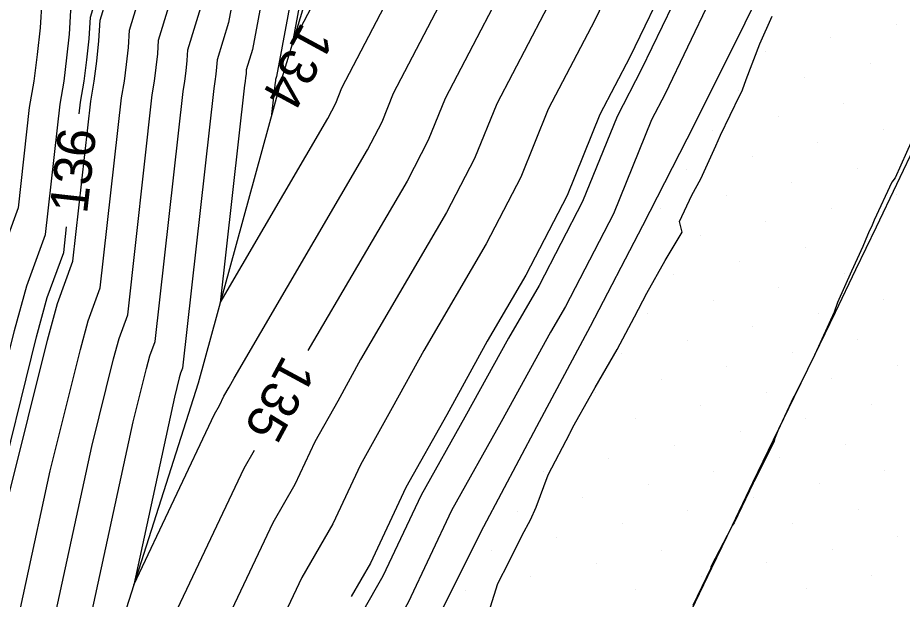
# Model space of a CAD drawing. Extents: x 2354170 to 2357230, y 866100 to 868290.
# Drawn here: x 2355357.59 to 2355404.32, y 866619.62 to 866650.36 of the extents above; entities that cross this region are included whole.
import ezdxf

# ---------------------------------------------------------------- set-up
doc = ezdxf.new("R2010")
doc.units = 0
for name, color, linetype in [('Default', 7, 'Continuous'), ('DTM Contours Major', 7, 'Continuous'), ('DTM Contours Major Text', 7, 'Continuous'), ('DTM Contours Minor', 7, 'Continuous'), ('DTM Contours Minor Text', 7, 'Continuous'), ('Exist DTM Breakline', 7, 'Continuous'), ('Exist DTM Scan Elevation Point', 7, 'Continuous'), ('Exist Roads EOP', 7, 'Continuous'), ('PH Exist DTM Breakline', 7, 'Continuous')]:
    doc.layers.add(name, color=color, linetype=linetype)

msp = doc.modelspace()

# ---------------------------------------------------------------- linework, layer by layer
at = {"layer": 'Default'}
for points in [[(2355404.065, 866738.574), (2355403.627, 866737.833), (2355401.527, 866732.928), (2355400.009, 866730.158), (2355397.579, 866724.896), (2355394.734, 866716.026), (2355394.481, 866711.128), (2355392.96, 866707.471), (2355385.279, 866694.958), (2355382.946, 866690.734), (2355381.332, 866685.936), (2355380.09, 866681.21), (2355379.533, 866679.416), (2355374.996, 866666.023), (2355374.18, 866663.538), (2355374.055, 866662.262), (2355371.262, 866647.255), (2355371.211, 866647.088), (2355371.209, 866647.056), (2355371.206, 866647.024), (2355371.202, 866646.992), (2355371.196, 866646.961), (2355371.004, 866645.244)], [(2355417.738, 866722.106), (2355417.021, 866720.646), (2355415.722, 866717.965), (2355412.295, 866710.557), (2355411.013, 866707.867), (2355409.724, 866705.182), (2355408.455, 866702.484), (2355402.934, 866690.579), (2355402.48, 866689.636), (2355402.023, 866688.698), (2355401.567, 866687.765), (2355401.116, 866686.825), (2355392.353, 866670.244), (2355391.996, 866669.464), (2355391.632, 866668.67), (2355391.256, 866667.866), (2355386.824, 866659.239), (2355385.588, 866656.686), (2355384.352, 866654.114), (2355380.171, 866646.091), (2355379.282, 866643.89), (2355378.157, 866641.72), (2355372.926, 866632.765)], [(2355419.453, 866709.399), (2355417.656, 866705.626), (2355415.584, 866701.31), (2355413.544, 866696.973), (2355411.332, 866692.203), (2355409.588, 866688.581), (2355407.834, 866684.98), (2355406.082, 866681.402), (2355404.351, 866677.793), (2355400.807, 866671.086), (2355399.182, 866667.535), (2355397.523, 866663.915), (2355395.809, 866660.253), (2355394.1, 866656.927), (2355392.017, 866652.622), (2355389.932, 866648.284), (2355388.346, 866645.241), (2355386.62, 866640.968), (2355384.435, 866636.753), (2355382.396, 866633.263), (2355380.253, 866629.369), (2355378.098, 866625.526), (2355376.222, 866621.537), (2355375.214, 866619.774)], [(2355340.097, 866569.762), (2355345.058, 866584.849), (2355347.967, 866599.319), (2355349.018, 866602.883), (2355352.47, 866612.436), (2355354.936, 866623.811), (2355357.42, 866633.827), (2355358.064, 866636.185), (2355359.058, 866638.898), (2355359.828, 866645.787), (2355360.04, 866647.011), (2355360.193, 866648.247), (2355360.331, 866649.485), (2355360.403, 866650.748), (2355362.395, 866657.273), (2355362.993, 866660.49), (2355363.757, 866668.285), (2355366.448, 866676.48), (2355367.185, 866680.007), (2355367.686, 866682.296), (2355369.976, 866687.74), (2355370.53, 866689.525), (2355370.598, 866689.784)], [(2355351.14, 866602.581), (2355351.335, 866603.24), (2355353.954, 866610.488), (2355357.124, 866625.11), (2355359.162, 866633.326), (2355359.69, 866635.261), (2355360.505, 866637.487), (2355361.452, 866645.955), (2355361.635, 866647.009), (2355361.766, 866648.072), (2355361.885, 866649.138), (2355361.947, 866650.225), (2355363.662, 866655.842), (2355364.574, 866660.743), (2355365.246, 866667.607), (2355368.997, 866679.028), (2355369.202, 866680.007), (2355369.341, 866680.642), (2355369.976, 866682.152), (2355371.895, 866688.337), (2355372.131, 866689.234)], [(2355347.664, 866575.561), (2355348.122, 866576.954), (2355353.108, 866601.753), (2355353.652, 866603.597), (2355355.438, 866608.54), (2355359.311, 866626.408), (2355360.903, 866632.826), (2355361.316, 866634.338), (2355361.953, 866636.076), (2355363.076, 866646.123), (2355363.229, 866647.006), (2355363.339, 866647.897), (2355363.439, 866648.791), (2355363.491, 866649.702), (2355364.928, 866654.411), (2355366.154, 866660.996), (2355366.735, 866666.929), (2355370.526, 866678.473), (2355371.024, 866679.942), (2355373.261, 866687.149), (2355373.665, 866688.685)], [(2355370.895, 866661.755), (2355368.729, 866650.117), (2355368.123, 866648.133), (2355368.101, 866647.75), (2355368.059, 866647.373), (2355368.013, 866646.998), (2355367.948, 866646.626), (2355366.295, 866631.844), (2355366.194, 866631.566), (2355366.128, 866631.326), (2355365.874, 866630.303), (2355363.726, 866620.393), (2355367.994, 866629.406), (2355368.252, 866629.858), (2355368.485, 866630.354), (2355368.754, 866630.833), (2355369.02, 866631.318), (2355376.065, 866643.376), (2355376.836, 866644.864), (2355377.446, 866646.374), (2355382.492, 866656.057)], [(2355372.475, 866662.008), (2355369.995, 866648.686), (2355369.667, 866647.611), (2355369.655, 866647.403), (2355369.632, 866647.199), (2355369.607, 866646.995), (2355369.572, 866646.793), (2355368.287, 866635.3), (2355373.972, 866645.032), (2355374.39, 866645.839), (2355374.721, 866646.657), (2355380.632, 866658.001)], [(2355389.874, 866653.977), (2355388.072, 866650.227), (2355385.621, 866645.524), (2355384.174, 866641.942), (2355382.342, 866638.409), (2355379.052, 866632.777), (2355377.378, 866629.735), (2355375.695, 866626.733), (2355374.23, 866623.618), (2355372.608, 866620.782), (2355366.535, 866607.955), (2355365.393, 866605.612), (2355364.257, 866603.287), (2355363.227, 866600.929), (2355362.276, 866598.487), (2355361.279, 866596.02), (2355349.553, 866576.781), (2355349.392, 866576.404), (2355349.209, 866576.028)], [(2355356.922, 866606.591), (2355361.499, 866627.706), (2355362.645, 866632.326), (2355362.942, 866633.414), (2355363.4, 866634.665), (2355364.7, 866646.29), (2355364.824, 866647.003), (2355364.912, 866647.723), (2355364.993, 866648.444), (2355365.035, 866649.179), (2355366.195, 866652.98)], [(2355386.212, 866652.171), (2355382.896, 866645.808), (2355381.728, 866642.916), (2355380.25, 866640.065), (2355375.708, 866632.29), (2355374.503, 866630.101), (2355373.292, 866627.94), (2355372.237, 866625.698), (2355371.07, 866623.657), (2355362.843, 866606.279), (2355362.233, 866605.029), (2355361.627, 866603.789), (2355361.078, 866602.531), (2355360.57, 866601.228), (2355360.038, 866599.912), (2355352.615, 866587.732)], [(2355358.859, 866651.27), (2355358.776, 866649.832), (2355358.619, 866648.421), (2355358.445, 866647.014), (2355358.204, 866645.619), (2355357.611, 866640.309), (2355356.438, 866637.109), (2355355.678, 866634.327), (2355352.748, 866622.513), (2355350.986, 866614.384), (2355346.701, 866602.525), (2355345.396, 866598.101), (2355343.525, 866588.797), (2355336.313, 866566.863)], [(2355370.078, 866627.487), (2355369.532, 866626.531), (2355359.15, 866604.604), (2355359.073, 866604.447), (2355358.997, 866604.291), (2355358.928, 866604.133), (2355358.864, 866603.969), (2355358.798, 866603.803), (2355357.865, 866602.273), (2355358.25, 866604.188), (2355358.286, 866604.312), (2355358.406, 866604.643), (2355363.687, 866629.004), (2355364.386, 866631.826), (2355364.568, 866632.49), (2355364.848, 866633.254), (2355366.324, 866646.458), (2355366.418, 866647), (2355366.486, 866647.548), (2355366.547, 866648.097), (2355366.579, 866648.656), (2355367.462, 866651.548)], [(2355394.159, 866651.267), (2355391.792, 866646.341), (2355391.071, 866644.958), (2355389.066, 866639.994), (2355386.527, 866635.098), (2355385.74, 866633.749), (2355383.127, 866629.002), (2355380.501, 866624.319), (2355378.215, 866619.457), (2355375.685, 866615.033), (2355373.92, 866611.306), (2355371.712, 866606.777), (2355369.517, 866602.284), (2355367.526, 866597.725), (2355365.687, 866593.005), (2355363.76, 866588.237), (2355360.548, 866582.968), (2355358.804, 866578.894), (2355356.826, 866574.822)], [(2355382.568, 866619.22), (2355382.955, 866620.456), (2355383.529, 866621.581), (2355384.239, 866623.008), (2355384.68, 866623.817), (2355384.977, 866624.484), (2355385.613, 866626.198), (2355386.753, 866628.379), (2355386.777, 866628.426), (2355386.798, 866628.463), (2355386.92, 866628.724), (2355387.853, 866630.384), (2355388.096, 866630.815), (2355389.264, 866632.823), (2355390.18, 866634.556), (2355390.818, 866635.794), (2355391.794, 866637.522), (2355392.701, 866639.03), (2355392.559, 866639.588), (2355393.206, 866640.985), (2355393.671, 866641.85), (2355394.479, 866643.596), (2355394.725, 866644.151), (2355395.739, 866646.266), (2355395.819, 866646.424), (2355395.874, 866646.548), (2355396.082, 866647.103), (2355396.799, 866648.979), (2355397.446, 866650.438)], [(2355404.843, 866643.913), (2355403.951, 866641.9), (2355403.77, 866641.664), (2355402.834, 866639.666), (2355402.726, 866639.4), (2355402.531, 866638.986), (2355402.475, 866638.872), (2355402.229, 866638.272), (2355401.635, 866636.964), (2355400.906, 866635.302), (2355400.725, 866634.796), (2355399.699, 866632.553), (2355399.697, 866632.55), (2355398.608, 866630.364), (2355398.582, 866630.304), (2355397.75, 866628.519), (2355397.577, 866628.085), (2355397.551, 866627.963), (2355396.471, 866625.832), (2355396.435, 866625.752), (2355395.434, 866623.658), (2355395.357, 866623.546), (2355395.355, 866623.539), (2355395.276, 866623.394), (2355394.233, 866621.367), (2355394.207, 866621.313), (2355394.188, 866621.233), (2355393.251, 866619.288)]]:
    msp.add_lwpolyline(points, dxfattribs=at)
at = {"layer": 'DTM Contours Major'}
for points in [[(2355417.738, 866722.106), (2355417.021, 866720.646), (2355415.722, 866717.965), (2355412.295, 866710.557), (2355411.013, 866707.867), (2355409.724, 866705.182), (2355408.455, 866702.484), (2355402.934, 866690.579), (2355402.48, 866689.636), (2355402.023, 866688.698), (2355401.567, 866687.765), (2355401.116, 866686.825), (2355392.353, 866670.244), (2355391.996, 866669.464), (2355391.632, 866668.67), (2355391.256, 866667.866), (2355386.824, 866659.239), (2355385.588, 866656.686), (2355384.352, 866654.114), (2355380.171, 866646.091), (2355379.282, 866643.89), (2355378.157, 866641.72), (2355372.926, 866632.765)], [(2355370.078, 866627.487), (2355369.532, 866626.531), (2355359.15, 866604.604), (2355359.073, 866604.447), (2355358.997, 866604.291), (2355358.928, 866604.133), (2355358.864, 866603.969), (2355358.798, 866603.803), (2355357.865, 866602.273), (2355358.25, 866604.188), (2355358.286, 866604.312), (2355358.406, 866604.643), (2355363.687, 866629.004), (2355364.386, 866631.826), (2355364.568, 866632.49), (2355364.848, 866633.254), (2355366.324, 866646.458), (2355366.418, 866647), (2355366.486, 866647.548), (2355366.547, 866648.097), (2355366.579, 866648.656), (2355367.462, 866651.548)]]:
    msp.add_lwpolyline(points, dxfattribs=at)
at = {"layer": 'DTM Contours Minor'}
for points in [[(2355360.842, 866645.279), (2355360.911, 866645.899), (2355361.103, 866647.009), (2355361.241, 866648.13), (2355361.367, 866649.254), (2355361.432, 866650.399), (2355363.239, 866656.319), (2355364.047, 866660.659), (2355364.75, 866667.833), (2355368.148, 866678.179), (2355368.529, 866680.007), (2355368.789, 866681.193), (2355369.976, 866684.015), (2355371.44, 866688.733), (2355371.62, 866689.418)], [(2355373.963, 866659.019), (2355372.09, 866648.959), (2355378.152, 866660.592), (2355378.446, 866661.202), (2355378.739, 866661.809), (2355380.269, 866664.785), (2355384.997, 866676.038), (2355387.149, 866678.155), (2355391.923, 866687.153)], [(2355396.9, 866660.658), (2355396.315, 866659.407), (2355394.909, 866656.67), (2355392.731, 866652.17), (2355390.552, 866647.636), (2355389.255, 866645.147), (2355387.435, 866640.643), (2355385.132, 866636.201), (2355383.511, 866633.425), (2355381.211, 866629.247), (2355378.899, 866625.124), (2355376.886, 866620.844), (2355374.659, 866616.95), (2355371.459, 866610.189), (2355369.605, 866606.389), (2355367.764, 866602.618), (2355366.093, 866598.793), (2355364.55, 866594.832), (2355362.933, 866590.832), (2355356.883, 866580.905), (2355355.667, 866578.064), (2355354.287, 866575.224)], [(2355342.619, 866571.695), (2355346.079, 866582.218), (2355349.681, 866600.13), (2355350.562, 866603.121), (2355353.46, 866611.137), (2355356.395, 866624.677), (2355358.581, 866633.493), (2355359.148, 866635.569), (2355360.023, 866637.958), (2355360.175, 866639.316)]]:
    msp.add_lwpolyline(points, dxfattribs=at)
at = {"layer": 'Exist DTM Breakline'}
msp.add_lwpolyline([(2355384.538, 866601.003), (2355385.616, 866603.259), (2355386.694, 866605.515), (2355387.773, 866607.77), (2355388.853, 866610.025), (2355389.934, 866612.279), (2355391.014, 866614.534), (2355392.095, 866616.788), (2355393.18, 866619.04), (2355394.264, 866621.293), (2355395.349, 866623.545), (2355396.434, 866625.798), (2355397.522, 866628.048), (2355398.61, 866630.299), (2355399.699, 866632.55), (2355400.786, 866634.801), (2355401.869, 866637.054), (2355402.951, 866639.308), (2355404.034, 866641.561), (2355405.116, 866643.815)], dxfattribs=at)
at = {"layer": 'Exist DTM Scan Elevation Point'}
for p, q in [((2355403.997, 866650.006), (2355403.997, 866650.006)), ((2355400.533, 866649.301), (2355400.533, 866649.301)), ((2355397.069, 866648.595), (2355397.069, 866648.595)), ((2355402.618, 866647.921), (2355402.618, 866647.921)), ((2355399.154, 866647.216), (2355399.154, 866647.216)), ((2355395.689, 866646.51), (2355395.689, 866646.51)), ((2355401.239, 866645.836), (2355401.239, 866645.836)), ((2355397.774, 866645.131), (2355397.774, 866645.131)), ((2355394.31, 866644.425), (2355394.31, 866644.425)), ((2355403.324, 866644.457), (2355403.324, 866644.457)), ((2355399.859, 866643.751), (2355399.859, 866643.751)), ((2355396.395, 866643.046), (2355396.395, 866643.046)), ((2355392.93, 866642.34), (2355392.93, 866642.34)), ((2355401.944, 866642.372), (2355401.944, 866642.372)), ((2355398.48, 866641.666), (2355398.48, 866641.666)), ((2355404.029, 866640.992), (2355404.029, 866640.992)), ((2355395.015, 866640.961), (2355395.015, 866640.961)), ((2355391.551, 866640.255), (2355391.551, 866640.255)), ((2355400.565, 866640.287), (2355400.565, 866640.287)), ((2355397.1, 866639.581), (2355397.1, 866639.581)), ((2355393.636, 866638.876), (2355393.636, 866638.876)), ((2355402.65, 866638.907), (2355402.65, 866638.907)), ((2355399.185, 866638.202), (2355399.185, 866638.202)), ((2355395.721, 866637.496), (2355395.721, 866637.496)), ((2355392.256, 866636.791), (2355392.256, 866636.791)), ((2355401.27, 866636.822), (2355401.27, 866636.822)), ((2355397.806, 866636.117), (2355397.806, 866636.117)), ((2355394.341, 866635.411), (2355394.341, 866635.411)), ((2355403.355, 866635.443), (2355403.355, 866635.443)), ((2355390.877, 866634.706), (2355390.877, 866634.706)), ((2355399.891, 866634.737), (2355399.891, 866634.737)), ((2355396.426, 866634.032), (2355396.426, 866634.032)), ((2355392.962, 866633.326), (2355392.962, 866633.326)), ((2355401.976, 866633.358), (2355401.976, 866633.358)), ((2355389.498, 866632.621), (2355389.498, 866632.621)), ((2355398.511, 866632.652), (2355398.511, 866632.652)), ((2355395.047, 866631.947), (2355395.047, 866631.947)), ((2355404.061, 866631.979), (2355404.061, 866631.979)), ((2355391.583, 866631.241), (2355391.583, 866631.241)), ((2355400.596, 866631.273), (2355400.596, 866631.273)), ((2355388.118, 866630.536), (2355388.118, 866630.536)), ((2355397.132, 866630.567), (2355397.132, 866630.567)), ((2355393.668, 866629.862), (2355393.668, 866629.862)), ((2355402.681, 866629.894), (2355402.681, 866629.894)), ((2355390.203, 866629.156), (2355390.203, 866629.156)), ((2355399.217, 866629.188), (2355399.217, 866629.188)), ((2355386.739, 866628.451), (2355386.739, 866628.451)), ((2355395.753, 866628.482), (2355395.753, 866628.482)), ((2355392.288, 866627.777), (2355392.288, 866627.777)), ((2355401.302, 866627.809), (2355401.302, 866627.809)), ((2355388.824, 866627.071), (2355388.824, 866627.071)), ((2355397.838, 866627.103), (2355397.838, 866627.103)), ((2355385.359, 866626.366), (2355385.359, 866626.366)), ((2355394.373, 866626.397), (2355394.373, 866626.397)), ((2355403.387, 866626.429), (2355403.387, 866626.429)), ((2355390.909, 866625.692), (2355390.909, 866625.692)), ((2355399.923, 866625.724), (2355399.923, 866625.724)), ((2355387.444, 866624.986), (2355387.444, 866624.986)), ((2355396.458, 866625.018), (2355396.458, 866625.018)), ((2355383.98, 866624.281), (2355383.98, 866624.281)), ((2355392.994, 866624.312), (2355392.994, 866624.312)), ((2355402.007, 866624.344), (2355402.007, 866624.344)), ((2355389.529, 866623.607), (2355389.529, 866623.607)), ((2355398.543, 866623.639), (2355398.543, 866623.639)), ((2355386.065, 866622.901), (2355386.065, 866622.901)), ((2355404.092, 866622.965), (2355404.092, 866622.965)), ((2355382.6, 866622.196), (2355382.6, 866622.196)), ((2355391.614, 866622.227), (2355391.614, 866622.227)), ((2355400.628, 866622.259), (2355400.628, 866622.259)), ((2355388.15, 866621.522), (2355388.15, 866621.522)), ((2355397.164, 866621.554), (2355397.164, 866621.554)), ((2355384.685, 866620.816), (2355384.685, 866620.816)), ((2355393.699, 866620.848), (2355393.699, 866620.848)), ((2355402.713, 866620.88), (2355402.713, 866620.88)), ((2355381.221, 866620.111), (2355381.221, 866620.111)), ((2355390.235, 866620.142), (2355390.235, 866620.142)), ((2355399.249, 866620.174), (2355399.249, 866620.174))]:
    msp.add_line(p, q, dxfattribs=at)
at = {"layer": 'Exist Roads EOP'}
msp.add_lwpolyline([(2355359.783, 866574.354), (2355362.274, 866579.812), (2355364.696, 866585.302), (2355367.045, 866590.823), (2355369.36, 866596.358), (2355371.763, 866601.855), (2355374.358, 866607.265), (2355376.945, 866612.679), (2355379.514, 866618.1), (2355382.209, 866623.461), (2355385.021, 866628.761), (2355387.845, 866634.055), (2355390.623, 866639.373), (2355393.34, 866644.723), (2355396.016, 866650.093), (2355398.666, 866655.476)], dxfattribs=at)
at = {"layer": 'PH Exist DTM Breakline'}
msp.add_lwpolyline([(2355400.072, 866711.56), (2355388.753, 866691.651), (2355384.892, 866684.66), (2355382.352, 866679.242), (2355376.222, 866662.609), (2355371.495, 866646.992), (2355367.119, 866631.041), (2355358.619, 866604.363), (2355347.647, 866573.973), (2355342.726, 866562.737), (2355339.575, 866553.722), (2355335.616, 866543.525), (2355330.204, 866530.05)], dxfattribs=at)

# ---------------------------------------------------------------- texts
at = {"layer": 'Default'}
for s, rotation, p in [('134', 241.546, (2355372.604, 866650.192)), ('135', 241.6524, (2355371.637, 866632.602))]:
    msp.add_text(s, height=2, rotation=rotation, dxfattribs=at).set_placement(p)
at = {"layer": 'DTM Contours Major Text'}
msp.add_text('135', height=2, rotation=241.6524, dxfattribs=at).set_placement((2355371.637, 866632.602))
at = {"layer": 'DTM Contours Minor Text'}
msp.add_text('136', height=2, rotation=83.6194, dxfattribs=at).set_placement((2355361.253, 866639.956))

doc.saveas('drawing.dxf')
